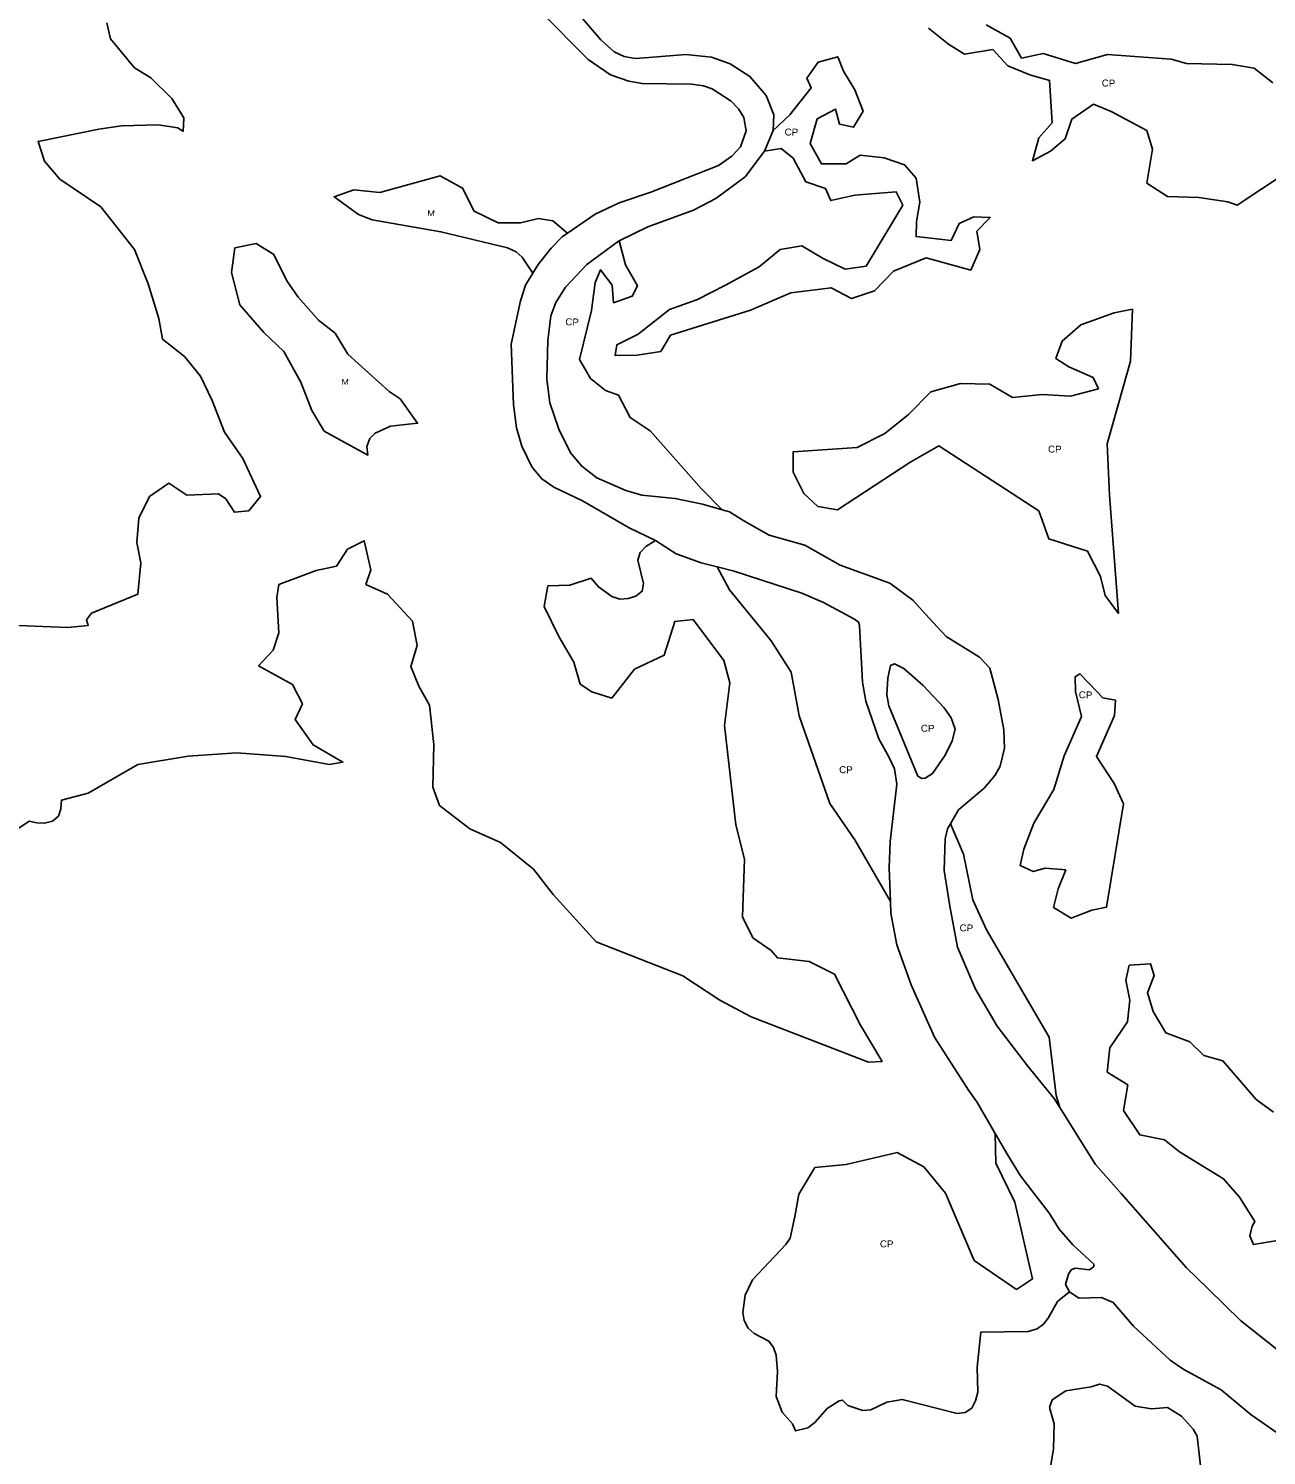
# Model space of a CAD drawing. Extents: x 713589 to 726391, y 7177764 to 7191819.
# Drawn here: x 723901 to 725036, y 7188896 to 7190205 of the extents above; entities that cross this region are included whole.
import ezdxf
from ezdxf.enums import TextEntityAlignment as Align

# ---------------------------------------------------------------- set-up
doc = ezdxf.new("R2010")
doc.units = 0
doc.header["$LTSCALE"] = 2.6
doc.layers.add('63', color=7, linetype='Continuous', lineweight=25)

msp = doc.modelspace()

# ---------------------------------------------------------------- linework, layer by layer
at = {"layer": '63'}
msp.add_line((724575.55, 7190092.42), (724583.66, 7190111.47), dxfattribs=at)
for points in [[(724583.66, 7190111.47), (724584.32, 7190125.79), (724577.12, 7190143.62), (724562.35, 7190161.02), (724544.18, 7190172.39), (724527.03, 7190178.78), (724503.61, 7190181.2), (724469.67, 7190178.5), (724457.01, 7190177.58), (724446.9, 7190179.38), (724437.79, 7190183.7), (724425.54, 7190194.47), (724401.08, 7190223.03), (724359.5, 7190278.99), (724341.57, 7190293.4), (724310.45, 7190313.84), (724296.96, 7190316.53), (724285.81, 7190315.74)], [(724370.22, 7190220.66), (724414, 7190176.62), (724434.46, 7190162.45), (724451.18, 7190156.57), (724463.41, 7190154.58), (724508.68, 7190153.87), (724519.8, 7190152.45), (724527.73, 7190149.62), (724545.22, 7190138.26), (724551.81, 7190131.37), (724556.65, 7190123.36), (724558.77, 7190111), (724553.57, 7190096.31), (724545.8, 7190087.76), (724533.56, 7190079.15), (724471.49, 7190054.96), (724442.45, 7190044.92), (724420.29, 7190034.71), (724394.95, 7190017.1)], [(723875.96, 7189657.82), (723936.61, 7189655.55), (723955.53, 7189657.49), (723953.76, 7189662.67), (723958.52, 7189668.55), (724000.81, 7189686.1), (724003.63, 7189714.94), (723999.93, 7189733.46), (724001.72, 7189755.72), (724011.73, 7189775.56), (724029.25, 7189787.84), (724046, 7189776.81), (724074.79, 7189778.08), (724081.63, 7189773.6), (724089.46, 7189761.24), (724102.83, 7189762.57), (724113.5, 7189775.55), (724097.17, 7189810.56), (724080.47, 7189834.6), (724069.26, 7189863.77), (724058.37, 7189886.08), (724043.7, 7189903.95), (724023.54, 7189920.13), (724020.18, 7189938.99), (724010.36, 7189970.89), (723997.79, 7190002.12), (723967.08, 7190041.29), (723929.48, 7190066.78), (723915.49, 7190083.27), (723909.52, 7190101.32), (723965.32, 7190112.67), (723986.01, 7190115.52), (724019.71, 7190116.51), (724037.71, 7190113.73), (724042.46, 7190110.49), (724043.1, 7190122.92), (724032.2, 7190140.78), (724012.73, 7190159.69), (723998.03, 7190168.99), (723975.85, 7190195.46), (723972.47, 7190210.2)], [(724779.02, 7190208.41), (724801.1, 7190196.07), (724811.5, 7190177.8), (724831.24, 7190181.92), (724860.8, 7190172.85), (724890.13, 7190181.11), (724948.71, 7190176.72), (724962.84, 7190172.91), (725004.59, 7190172.04), (725024.61, 7190168.69), (725041.9, 7190155.17)], [(725054.47, 7190072.92), (725009.22, 7190042.88), (725000.56, 7190045.9), (724973.97, 7190049.88), (724945.28, 7190050.88), (724926.19, 7190063.2), (724931.38, 7190094.28), (724926.36, 7190111.33), (724893.53, 7190128.79), (724877.41, 7190135.42), (724857.64, 7190121.74), (724851.3, 7190103.82), (724838.1, 7190092.51), (724821.33, 7190083.6), (724827.38, 7190104.8), (724839.39, 7190118.51), (724837.13, 7190157.38), (724818.92, 7190162.53), (724798.92, 7190170.67), (724785.22, 7190185.67), (724759.19, 7190181.27), (724744.58, 7190190.59), (724726.09, 7190205.3)], [(724583.66, 7190111.47), (724599.06, 7190125.63), (724618.58, 7190150.68), (724614.43, 7190159.36), (724624.94, 7190173.97), (724642.9, 7190178.99), (724648.23, 7190165.82), (724658.63, 7190148.74), (724666.04, 7190128.99), (724657.32, 7190114.37), (724644.47, 7190117.1), (724640.93, 7190130.87), (724623.86, 7190121.96), (724617.51, 7190099.56), (724627.9, 7190080.69), (724650.62, 7190080.91), (724663.51, 7190088.64), (724685.32, 7190086.17), (724704.13, 7190079.83), (724714.85, 7190067.53), (724718.06, 7190045.7), (724715.01, 7190027.77), (724714.66, 7190014.02), (724746.94, 7190010.62), (724754.17, 7190026.14), (724767.64, 7190032.07), (724782.59, 7190031.72), (724770.28, 7190018.91), (724773.21, 7190002.16), (724764.78, 7189983.35), (724723.86, 7189994.56), (724693.93, 7189982.41), (724676.52, 7189964.23), (724655.57, 7189957.43), (724636.77, 7189967.06), (724599.69, 7189962.41), (724562.86, 7189946.69), (724489.54, 7189923.63), (724480.52, 7189908.72), (724458.99, 7189905.2), (724438.66, 7189904.98), (724440.19, 7189914.84), (724459.95, 7189924.63), (724488.43, 7189947.25), (724514.17, 7189956.43), (724539.92, 7189969.49), (724570.78, 7189986.42), (724589.96, 7190002.2), (724610, 7190005.72), (724629.39, 7189993.99), (724649.69, 7189984.06), (724668.83, 7189986.98), (724702.51, 7190042.76), (724696.57, 7190055.04), (724658.6, 7190052.18), (724636.46, 7190047.18), (724631.71, 7190058.26), (724613.5, 7190064.3), (724601.91, 7190085.86), (724590.89, 7190094.87), (724575.55, 7190092.42)], [(724442.34, 7190010.13), (724468.75, 7190022.96), (724510.52, 7190038.28), (724530.94, 7190048.9), (724557.94, 7190068.96), (724575.55, 7190092.42)], [(724363.3, 7189980.66), (724353.42, 7189995.14), (724347.79, 7190000.2), (724340.04, 7190003.76), (724278.85, 7190018.5), (724215.73, 7190029.42), (724203.34, 7190034.4), (724180.89, 7190050.63), (724199.12, 7190056.92), (724222.76, 7190054.44), (724278.33, 7190069.67), (724298.85, 7190058.63), (724309.39, 7190037.35), (724331.29, 7190026.65), (724351.85, 7190026.58), (724368.31, 7190030.63), (724381.67, 7190028.53), (724394.95, 7190017.1)], [(724394.95, 7190017.1), (724390.1, 7190013.73), (724379.9, 7190003.6), (724368.02, 7189988.33), (724363.3, 7189980.66)], [(724536.82, 7189763.46), (724518.68, 7189768.5), (724493.73, 7189773.79), (724463.3, 7189776.92), (724448.51, 7189781.03), (724421.84, 7189792.65), (724408.13, 7189803.42), (724397.78, 7189815.64), (724386.94, 7189837.39), (724378.9, 7189861.46), (724376.15, 7189883.38), (724376.88, 7189918.69), (724379.79, 7189941.3), (724384.22, 7189953.67), (724393.17, 7189967.76), (724412.84, 7189988.38), (724441.84, 7190009.89), (724442.34, 7190010.13)], [(724536.82, 7189763.46), (724517.75, 7189782.73), (724470.7, 7189835.81), (724452.51, 7189848.13), (724441.82, 7189868.49), (724429.88, 7189873.02), (724416.16, 7189883.83), (724406.06, 7189901.2), (724416.98, 7189946.31), (724420.36, 7189972), (724425.18, 7189983.65), (724435.89, 7189969.56), (724437.33, 7189953.41), (724454.39, 7189959.33), (724459.21, 7189968.88), (724448.21, 7189988.05), (724442.34, 7190010.13)], [(724363.3, 7189980.66), (724356.4, 7189969.46), (724351.76, 7189955.2), (724343.35, 7189915.38), (724345.55, 7189860.01), (724348.3, 7189838.76), (724353.06, 7189821.92), (724362.38, 7189802.82), (724371.37, 7189791.77), (724382.39, 7189784.16), (724408.8, 7189771.84), (724451.44, 7189747.07), (724475.68, 7189735.46)], [(724746.17, 7189475.5), (724753.52, 7189488.23), (724777.25, 7189508.15), (724787.33, 7189519.94), (724791.87, 7189528.37), (724795.91, 7189544.85), (724795.04, 7189561.68), (724790.02, 7189589.59), (724782.25, 7189618.3), (724772.98, 7189628.32), (724742.27, 7189647.16), (724726.82, 7189664.17), (724711.85, 7189680.59), (724690.56, 7189696.2), (724645.17, 7189712.73), (724612.6, 7189730.9), (724579.89, 7189740.24), (724556.64, 7189753.36), (724543.65, 7189761.56), (724536.82, 7189763.46)], [(723882.41, 7189464.87), (723901.33, 7189477.78), (723908.27, 7189476.34), (723915.33, 7189475.91), (723922.8, 7189477.85), (723928.26, 7189482.47), (723930.3, 7189489.22), (723930.9, 7189497.08), (723955.54, 7189503.68), (724000.86, 7189529.91), (724047.15, 7189537.63), (724091.71, 7189540.56), (724136.58, 7189537.31), (724176.31, 7189529.98), (724188.99, 7189531.99), (724161.64, 7189547.85), (724145.27, 7189571.21), (724151.83, 7189585.58), (724142.64, 7189603.09), (724111.66, 7189620.38), (724125.12, 7189634.68), (724130.17, 7189650.75), (724128.32, 7189683.04), (724130.13, 7189694.81), (724164.6, 7189707.86), (724183.11, 7189711.91), (724193.1, 7189727.3), (724208.55, 7189735.12), (724214.63, 7189708.37), (724210.13, 7189695.03), (724229.97, 7189686.05), (724252.84, 7189661.3), (724257.22, 7189639.01), (724251.32, 7189619.84), (724258.8, 7189601.65), (724268.33, 7189584.14), (724272.32, 7189548.15), (724271.5, 7189509.09), (724277.61, 7189492.27), (724305.29, 7189470.93), (724333.68, 7189458.15), (724363.75, 7189433.72), (724381.83, 7189410.7), (724421.43, 7189367.04), (724500.82, 7189335.92), (724534.67, 7189313.53), (724563.4, 7189298.35), (724671.19, 7189256.85), (724683.53, 7189257.5), (724663.77, 7189290.8), (724639.95, 7189337.49), (724616.69, 7189349.22), (724587.57, 7189352.41), (724581.77, 7189359.28), (724565.02, 7189370.99), (724555.5, 7189390.21), (724557.39, 7189442.98), (724549.28, 7189474.53), (724538.98, 7189565.72), (724543.91, 7189604.76), (724538.5, 7189625.34), (724510.19, 7189662.79), (724493.39, 7189661.14), (724483.69, 7189629.99), (724456.57, 7189617.41), (724435.58, 7189590.75), (724417.44, 7189596.64), (724406.5, 7189603.53), (724400.74, 7189623.77), (724387.12, 7189647.12), (724373.51, 7189674.92), (724377, 7189693.76), (724397.22, 7189694.37), (724416.67, 7189700.8), (724423.39, 7189692.8), (724435.62, 7189683.83), (724442.97, 7189681.43), (724450.69, 7189682.01), (724457.66, 7189684.11), (724463.63, 7189688.78), (724464.56, 7189695.94), (724459.6, 7189717.39), (724461.54, 7189724.25), (724466.75, 7189729.67), (724475.68, 7189735.46)], [(724475.68, 7189735.46), (724494.61, 7189722.99), (724517.74, 7189714.94), (724532.2, 7189711.25)], [(724532.2, 7189711.25), (724543.52, 7189690.09), (724581.74, 7189643.35), (724600.14, 7189614.51), (724607.54, 7189574.39), (724635.7, 7189494.1), (724658.54, 7189460.79), (724691.23, 7189404.06)], [(724532.2, 7189711.25), (724547.92, 7189707.24), (724609.97, 7189686.92), (724629.64, 7189678.55), (724658.18, 7189663.07), (724661.76, 7189660.43), (724662.89, 7189657.25), (724665.5, 7189605.46), (724668.75, 7189588), (724680.68, 7189553.4), (724689.88, 7189536.22), (724694.83, 7189525.74), (724696.93, 7189511.93), (724690.97, 7189459.29), (724689.93, 7189435.01), (724691.23, 7189404.06)], [(724846.57, 7189215.13), (724841.31, 7189223.51), (724817.03, 7189253.29), (724788.99, 7189289.94), (724769.19, 7189323.88), (724752.68, 7189362.4), (724745.54, 7189399.76), (724740.56, 7189432.71), (724741.52, 7189461.54), (724743.55, 7189470.96), (724746.17, 7189475.5)], [(724746.17, 7189475.5), (724758.12, 7189447.67), (724766.64, 7189405.79), (724779.4, 7189378.24), (724836.75, 7189279.69), (724843.14, 7189226.16), (724846.57, 7189215.13)], [(724691.23, 7189404.06), (724691.67, 7189393.51), (724697.04, 7189364.31), (724710.21, 7189327.87), (724731.55, 7189279.62), (724762.74, 7189231.03), (724770.36, 7189220.42), (724787.35, 7189191.28)], [(725042.42, 7189210.93), (725026.62, 7189222.64), (724995.95, 7189258.03), (724978.63, 7189262.87), (724965.82, 7189275.47), (724943.73, 7189283.62), (724932.14, 7189303.39), (724926.82, 7189320.45), (724933.15, 7189336.27), (724929.6, 7189347.04), (724910.16, 7189345.62), (724907.13, 7189331.88), (724910.65, 7189313.63), (724908.49, 7189293.91), (724892.26, 7189270.05), (724890.09, 7189247.64), (724908.88, 7189235.91), (724904.91, 7189212.31), (724919.78, 7189190.13), (724942.49, 7189185.57), (724956.2, 7189174.46), (724996.77, 7189149.81), (725011.36, 7189133.01), (725025.42, 7189110.72), (725022.91, 7189106.26), (725020.81, 7189097.37), (725024.27, 7189089.54), (725071.92, 7189097.53)], [(725346.67, 7188902.16), (725310.08, 7188902.07), (725281, 7188906.55), (725251.11, 7188914.36), (725182.41, 7188926.85), (725152.82, 7188934.31), (725126.3, 7188945.42), (725091.35, 7188967.44), (725046.11, 7188993), (725012.14, 7189019.88), (724982.59, 7189048.78), (724962.75, 7189068.19), (724902.69, 7189136.36), (724879.35, 7189162.89), (724846.57, 7189215.13)], [(724787.35, 7189191.28), (724787.72, 7189164.27), (724805.41, 7189128.23), (724821.61, 7189057.92), (724806.85, 7189048.38), (724767.87, 7189074.9), (724741.71, 7189136.67), (724721.91, 7189160.73), (724697.29, 7189173.84), (724650.65, 7189163.03), (724621.85, 7189160.05), (724607.03, 7189135.77), (724603.38, 7189115.1), (724599.29, 7189095.39), (724595.32, 7189089.45), (724564.6, 7189057.09), (724558, 7189043.22), (724555.68, 7189027.04), (724557, 7189019.77), (724560.63, 7189012.84), (724566.25, 7189007.88), (724579.78, 7189000.94), (724584.08, 7188995), (724586.39, 7188988.06), (724587.7, 7188973.2), (724586.38, 7188950.08), (724591.99, 7188935.88), (724601.23, 7188924.98), (724604.06, 7188918.69), (724615.31, 7188921.39), (724621.76, 7188926.14), (724633.15, 7188939.13), (724644.18, 7188946.11), (724647.29, 7188946.89), (724652.09, 7188941.81), (724665.96, 7188937.19), (724673.23, 7188937.85), (724687.76, 7188944.78), (724701.96, 7188947.42), (724752.49, 7188934.53), (724759.75, 7188935.52), (724765.7, 7188939.48), (724769.33, 7188946.08), (724771.32, 7188954.01), (724770.66, 7188977.13), (724774.18, 7189009.27), (724817.35, 7189009.61), (724825.63, 7189012.32), (724831.67, 7189016.55), (724835.93, 7189021.88), (724844.51, 7189037.27), (724855.4, 7189046.03)], [(724787.35, 7189191.28), (724798.8, 7189171.64), (724810.37, 7189152.65), (724837.04, 7189118.08), (724845.91, 7189103.72), (724858.54, 7189089.12), (724877.88, 7189071.3), (724877.37, 7189068.91), (724873.87, 7189066.28), (724860.53, 7189067.81), (724857.04, 7189066.28), (724854.41, 7189062.24), (724851.78, 7189052.94), (724855.4, 7189046.03)], [(725060.96, 7188906.39), (725022.08, 7188933.35), (724994.62, 7188956.12), (724960.37, 7188974.84), (724947.66, 7188983.43), (724913.96, 7189014.75), (724895.53, 7189036.38), (724884.62, 7189041.05), (724864.1, 7189040.46), (724855.4, 7189046.03)], [(724976.71, 7188875.7), (724972.43, 7188913.67), (724968.8, 7188920.28), (724958.23, 7188932.17), (724945.35, 7188940.1), (724930.49, 7188938.78), (724915.63, 7188941.1), (724890.21, 7188959.6), (724882.94, 7188961.58), (724875.35, 7188958.94), (724851.9, 7188955.31), (724839.35, 7188947.06), (724837.03, 7188940.12), (724841.32, 7188924.93), (724840.66, 7188902.14), (724838.34, 7188887.28)]]:
    msp.add_lwpolyline(points, dxfattribs=at)
for points in [[(724094.58, 7189951.4), (724116.43, 7189925.97), (724134.87, 7189908.77), (724150.53, 7189880.62), (724160.38, 7189854.54), (724171.96, 7189835.65), (724211.85, 7189813.6), (724210.82, 7189821.67), (724213.57, 7189828.77), (724218.73, 7189833.85), (724232.58, 7189840.21), (724257.58, 7189842.9), (724241.63, 7189865.22), (724231.37, 7189872.11), (724193.46, 7189906.17), (724181.87, 7189925.4), (724166.5, 7189937.45), (724148.06, 7189958.41), (724137.49, 7189973.53), (724125.59, 7189997.56), (724109.52, 7190007.89), (724089.97, 7190003.85), (724086.81, 7189981.24)], [(724660.77, 7189820.5), (724685.93, 7189833.56), (724707.81, 7189850.82), (724728.22, 7189871.68), (724755.45, 7189879.35), (724782.35, 7189878.66), (724803.23, 7189866.33), (724830.45, 7189869.23), (724856.45, 7189867.64), (724881.88, 7189874.43), (724877.14, 7189884.91), (724854.75, 7189894.55), (724842.82, 7189902.37), (724848.55, 7189918.19), (724865.65, 7189933.08), (724896.47, 7189944.03), (724913.15, 7189947.42), (724911.27, 7189899.73), (724890.08, 7189823.88), (724892, 7189776.94), (724900.29, 7189668.39), (724888.09, 7189684.88), (724883.97, 7189702.23), (724871.79, 7189725.59), (724836.56, 7189736.77), (724827.38, 7189762.51), (724735.52, 7189822.03), (724709.76, 7189807.47), (724642.64, 7189763.46), (724624.71, 7189766.51), (724611.9, 7189778.52), (724602.1, 7189797.98), (724601.87, 7189816.52)], [(724750.41, 7189562.36), (724746.91, 7189572.51), (724740.49, 7189581.69), (724720.86, 7189602.59), (724703.51, 7189617.76), (724694.88, 7189622.18), (724691.27, 7189620.8), (724688.69, 7189608.95), (724687.77, 7189593.85), (724689.6, 7189583.76), (724716.18, 7189519.27), (724719.93, 7189517.09), (724723.06, 7189517.33), (724729.84, 7189521.72), (724741.45, 7189538.28), (724747.67, 7189551.47)], [(724852.18, 7189433.11), (724833.05, 7189434.67), (724821.98, 7189431.72), (724810.04, 7189437.15), (724813.38, 7189452.08), (724822.73, 7189475.96), (724841.08, 7189506.99), (724850.45, 7189537.75), (724866.42, 7189573.86), (724860.82, 7189596.9), (724860.57, 7189610.36), (724864.97, 7189612.98), (724873.36, 7189604.1), (724885.91, 7189590.84), (724897.56, 7189589), (724896.62, 7189574.66), (724880.04, 7189537.05), (724896.4, 7189512.48), (724905, 7189493.91), (724889.42, 7189398.9), (724875.96, 7189396.26), (724856.8, 7189388.85), (724840.7, 7189398.77), (724844.94, 7189415.8)]]:
    msp.add_lwpolyline(points, close=True, dxfattribs=at)

# ---------------------------------------------------------------- texts
for s, height, width, p in [('CP', 6.4, 1.05, (724891.1, 7190151.7)), ('CP', 6.4, 1.05, (724600.31, 7190106.73)), ('M', 5.2, 1.2, (724269.89, 7190033)), ('CP', 6.4, 1.05, (724399.21, 7189932.61)), ('M', 5.2, 1.2, (724190.99, 7189878.34)), ('CP', 6.4, 1.05, (724841.88, 7189815.86)), ('CP', 6.4, 1.05, (724870.09, 7189590.51)), ('CP', 6.4, 1.05, (724725.23, 7189559.83)), ('CP', 6.4, 1.05, (724650.28, 7189521.85)), ('CP', 6.4, 1.05, (724760.8, 7189376.73)), ('CP', 6.4, 1.05, (724687.67, 7189086.94))]:
    msp.add_text(s, height=height, rotation=359.062, dxfattribs=dict(at, width=width)).set_placement(p, align=Align.CENTER)

doc.saveas('drawing.dxf')
